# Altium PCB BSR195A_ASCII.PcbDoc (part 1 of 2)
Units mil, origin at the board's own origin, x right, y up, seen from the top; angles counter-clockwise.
Board outline 4000 x 3000 mil, 4 copper layers (Top Layer, Signal Layer 1, Signal Layer 2, Bottom Layer), stack 64.4 mil thick; 59 components, 14 nets, 91 pads, 35 vias.
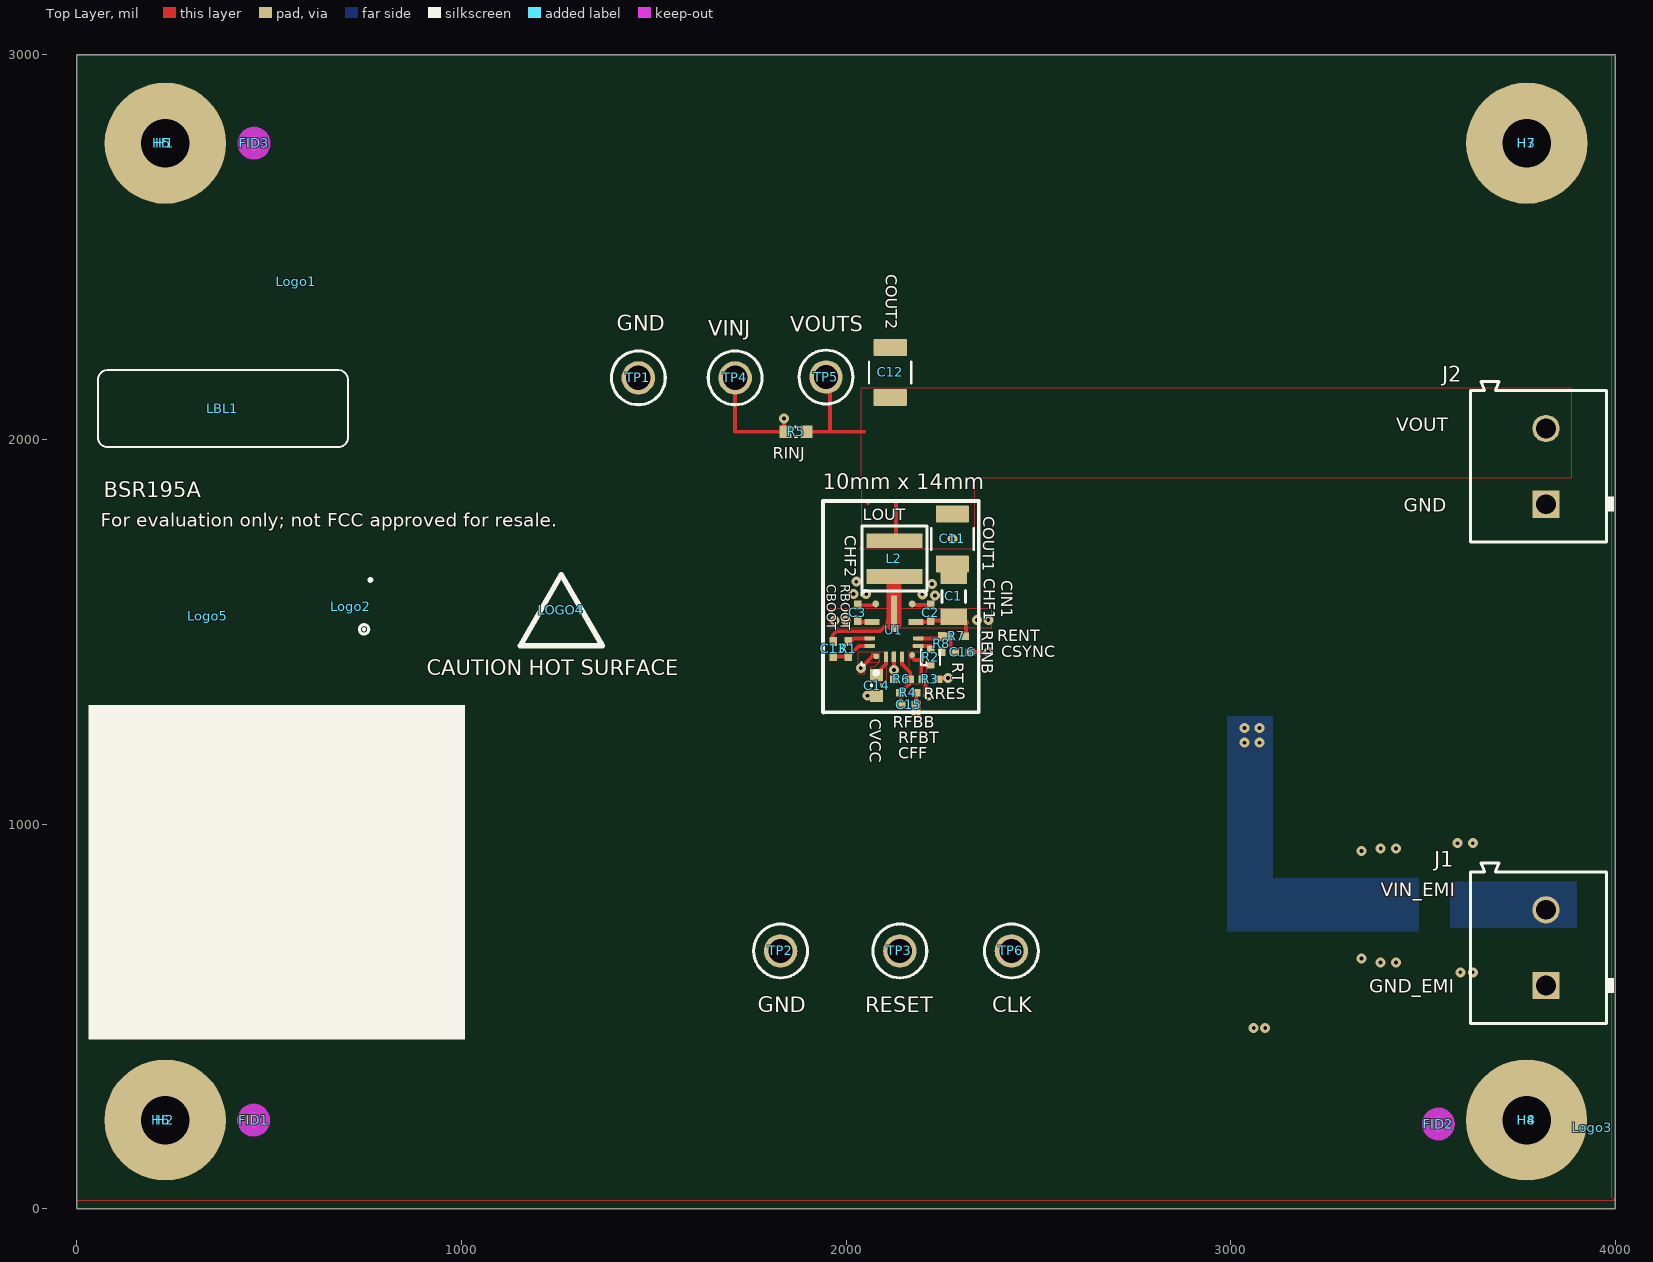
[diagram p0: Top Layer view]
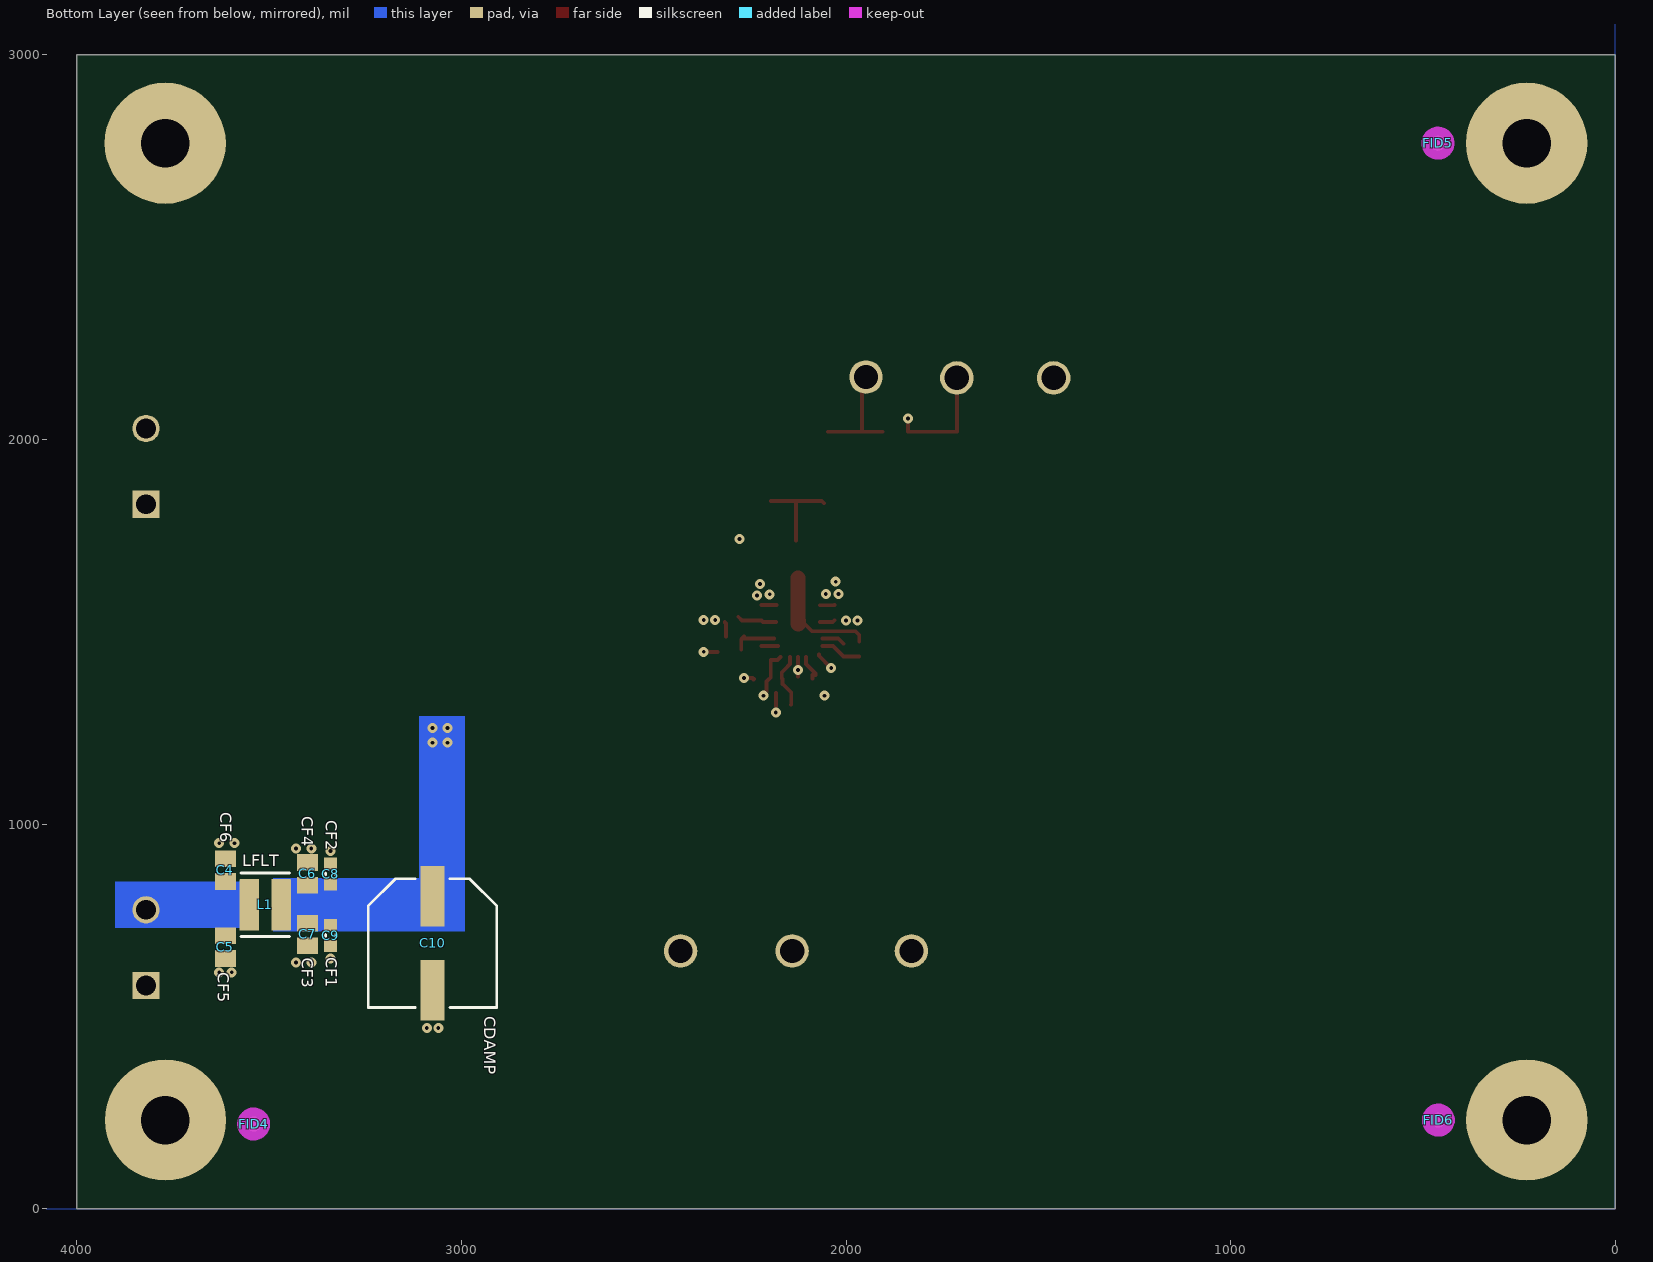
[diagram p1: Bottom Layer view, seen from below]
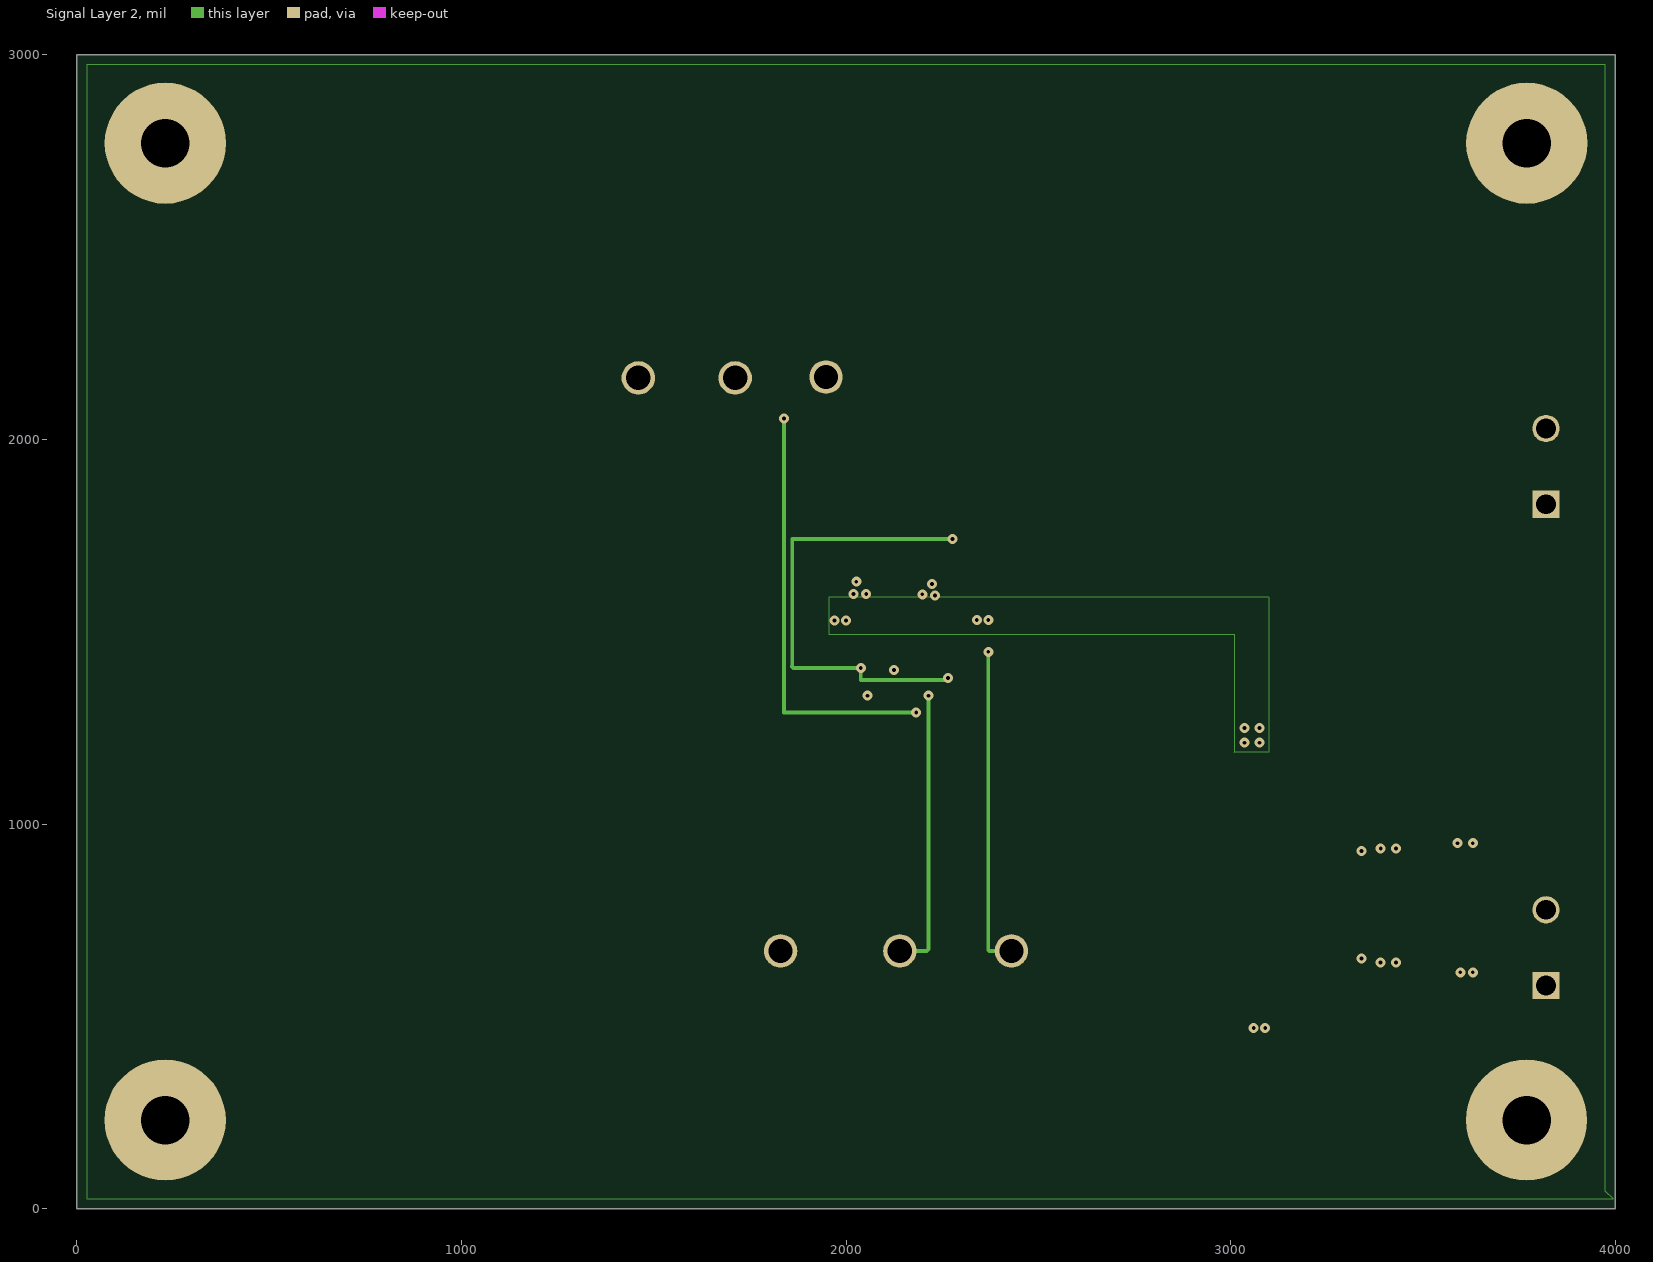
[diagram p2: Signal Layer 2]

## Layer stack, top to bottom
Top Solder: solder mask 0.4, Solder Resist, Dk 3.5
Top Layer: signal copper 2.8
Dielectric 1: prepreg 8, FR-4 High Tg, Dk 4.2
Signal Layer 1: signal copper 1.4
Dielectric 2: core 40, FR-4 High Tg, Dk 4.2
Signal Layer 2: signal copper 1.4
Dielectric 3: prepreg 8, FR-4 High Tg, Dk 4.2
Bottom Layer: signal copper 2.8
Bottom Solder: solder mask 0.4, Solder Resist, Dk 3.5

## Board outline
0,0 0,3000 4000,3000 4000,0

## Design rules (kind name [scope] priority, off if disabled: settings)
AcuteAngle [All] p0: scope1count=1 scope1_0_kind=Board scope1_0_value=Board scope2count=1 scope2_0_kind=Board scope2_0_value=Board commentlength=0 minimum=4.50000000000000E+0001
AcuteAngle [All] p1: minimum=4.50000000000000E+0001 checktracksonly=FALSE
AssemblyTestPointUsage [All] p0: scope1count=1 scope1_0_kind=Board scope1_0_value=Board scope2count=1 scope2_0_kind=Board scope2_0_value=Board commentlength=0
AssemblyTestPointUsage [All] p1: valid=2
AssemblyTestpoint [All] p0: scope1count=1 scope1_0_kind=Board scope1_0_value=Board scope2count=1 scope2_0_kind=Board scope2_0_value=Board commentlength=0
BoardOutlineClearance BoardOutlineClearance_MountingHoles [All] p0 off: scope1count=1 scope1_0_kind=Board scope1_0_value=Board scope2count=1 scope2_0_kind=Board scope2_0_value=Board commentlength=86 gap=40 // Protel DXP Scope 1 Expression Was: OnCopper and InComponentClass('Mounting Holes')
BoardOutlineClearance BoardOutlineClearance_Poly [All] p0 off: scope1count=1 scope1_0_kind=Board scope1_0_value=Board scope2count=1 scope2_0_kind=Board scope2_0_value=Board commentlength=58 gap=25 // Protel DXP Scope 1 Expression Was: OnCopper and IsPoly
BoardOutlineClearance [All] p0 off: scope1count=1 scope1_0_kind=Board scope1_0_value=Board scope2count=1 scope2_0_kind=Board scope2_0_value=Board commentlength=172 gap=65 // Protel DXP Scope 1 Expression Was: OnCopper and Not InComponentClass('Logo') and not InComponentClass('FiducialMark') and not InRegion(1000,500,4000,800) and not InPoly
BoardOutlineClearance BoardOutlineClearance_1 [All] p0: scope1count=1 scope1_0_kind=Footprint scope1_0_value=Edge_Connector_EDAC_12x2 scope2count=1 scope2_0_kind=Board scope2_0_value=Board commentlength=0 gap=0
BoardOutlineClearance BoardOutlineClearance_1 [HasFootprint('Edge_Connector_EDAC_12x2')] p1: gap=0 ignorepadtopadclearanceinfootprint=FALSE
BoardOutlineClearance BoardOutlineClearance_MountingHoles [OnCopper and InComponentClass('Mounting Holes')] p2: gap=40 ignorepadtopadclearanceinfootprint=FALSE
BoardOutlineClearance BoardOutlineClearance_Poly [OnCopper and IsPoly] p3: gap=25 ignorepadtopadclearanceinfootprint=FALSE
BoardOutlineClearance [OnCopper and Not InComponentClass('Logo') and not InComponentClass('FiducialMark') and not InRegion(1000,500,4000,800) and not InPoly] p4: gap=65 ignorepadtopadclearanceinfootprint=FALSE
Clearance "Stitching VIN_PIN" [All] p0 off: scope1count=1 scope1_0_kind=Board scope1_0_value=Board scope2count=1 scope2_0_kind=Board scope2_0_value=Board commentlength=80 gap=9 // Protel DXP Scope 2 Expression Was: (IsVia and (Not IsStitchingVia)) Or IsPad
Clearance Clearance_Keepouts [All] p0 off: scope1count=1 scope1_0_kind=Board scope1_0_value=Board scope2count=1 scope2_0_kind=Board scope2_0_value=Board commentlength=99 gap=0 // Protel DXP Scope 2 Expression Was: ((IsTrack Or IsArc) And Not InPoly) And IsFree and IsKeepOut
Clearance Clearance_Poly [All] p0 off: scope1count=1 scope1_0_kind=Board scope1_0_value=Board scope2count=1 scope2_0_kind=Board scope2_0_value=Board commentlength=48 gap=10 // Protel DXP Scope 1 Expression Was: InPolygon
Clearance Clearance_FiducialMark [All] p0 off: scope1count=1 scope1_0_kind=Board scope1_0_value=Board scope2count=1 scope2_0_kind=Board scope2_0_value=Board commentlength=81 gap=0 // Protel DXP Scope 2 Expression Was: IsPad and InComponentClass('FiducialMark')
Clearance [All] p0: scope1count=1 scope1_0_kind=Board scope1_0_value=Board scope2count=1 scope2_0_kind=Board scope2_0_value=Board commentlength=0 gap=7.87
Clearance "Stitching VIN_PIN" [IsStitchingVia and InNet('VIN_PIN') vs (IsVia and (Not IsStitchingVia)) Or IsPad] p1: gap=9 ignorepadtopadclearanceinfootprint=FALSE
Clearance Clearance_Keepouts [((IsTrack Or IsArc) And Not InPoly) And IsFree and IsKeepOut vs ((IsTrack Or IsArc) And Not InPoly) And IsFree and IsKeepOut] p2: gap=0 ignorepadtopadclearanceinfootprint=FALSE
Clearance Clearance_Poly [InPolygon] p3: gap=10 ignorepadtopadclearanceinfootprint=FALSE
Clearance Clearance_FiducialMark [IsKeepOut and InComponentClass('FiducialMark') vs IsPad and InComponentClass('FiducialMark')] p4: gap=0 ignorepadtopadclearanceinfootprint=FALSE
Clearance [All] p5: gap=7.87 ignorepadtopadclearanceinfootprint=FALSE except(0: Arc-Hole Track-Hole SMDPad-Hole THPad-Hole Via-Hole Fill-Hole Poly-Hole Region-Hole Text-Hole)
ComponentClearance ComponentClearance_Shunt [All] p0: scope1count=1 scope1_0_kind=ComponentClass scope1_0_value=Header scope2count=1 scope2_0_kind=ComponentClass scope2_0_value=Shunt commentlength=0 gap=0 collisioncheckmode=3
ComponentClearance ComponentClearance_Logo [All] p0: scope1count=1 scope1_0_kind=ComponentClass scope1_0_value=Logo scope2count=1 scope2_0_kind=Board scope2_0_value=Board commentlength=0 gap=50 collisioncheckmode=3
ComponentClearance ComponentClearance_ScrewToNut [All] p0 off: scope1count=1 scope1_0_kind=Board scope1_0_value=Board scope2count=1 scope2_0_kind=Board scope2_0_value=Board commentlength=71 gap=5 collisioncheckmode=3 // Protel DXP Scope 2 Expression Was: (HasFootprint('Keystone_1902C'))
ComponentClearance ComponentClearance_MountingHoles [All] p0: scope1count=1 scope1_0_kind=ComponentClass scope1_0_value="Mounting Holes" scope2count=1 scope2_0_kind=Board scope2_0_value=Board commentlength=0 gap=0 collisioncheckmode=3
ComponentClearance ComponentClearance_SmallPassives [All] p0 off: scope1count=1 scope1_0_kind=Board scope1_0_value=Board scope2count=1 scope2_0_kind=Board scope2_0_value=Board commentlength=508 gap=5 collisioncheckmode=3 // Protel DXP Scope 2 Expression Was: HasFootprint('0201*') or HasFootprint('0402*') or HasFootprint('0508') or HasFootprint('0603*') or HasFootprint('0612') or HasFootprint('0805*') or HasFootprint('0815*') or HasFootprint('0830*') or HasFootprint('1206*') or HasFootprint('1210*') or HasFootprint('1808*') or HasFootprint('1812*') or HasFootprint('1825*') or HasFootprint('2010*') or HasFootprint('2220*') or HasFootprint('2225*') or HasFootprint('2512*') or HasFootprint('2728*') or HasFootprint('3518*')
ComponentClearance ComponentClearance_THtoSMT [All] p0 off: scope1count=1 scope1_0_kind=Board scope1_0_value=Board scope2count=1 scope2_0_kind=Board scope2_0_value=Board commentlength=53 gap=40 collisioncheckmode=3 // Protel DXP Scope 2 Expression Was: IsSMTComponent
ComponentClearance ComponentClearance_THtoTH [All] p0 off: scope1count=1 scope1_0_kind=Board scope1_0_value=Board scope2count=1 scope2_0_kind=Board scope2_0_value=Board commentlength=54 gap=30 collisioncheckmode=3 // Protel DXP Scope 2 Expression Was: IsThruComponent
ComponentClearance [All] p0: scope1count=1 scope1_0_kind=Board scope1_0_value=Board scope2count=1 scope2_0_kind=Board scope2_0_value=Board commentlength=0 gap=5 collisioncheckmode=3
ComponentClearance ComponentClearance_1 [All] p0: scope1count=1 scope1_0_kind=Component scope1_0_value=SH-J1 scope2count=1 scope2_0_kind=Board scope2_0_value=Board commentlength=0 gap=0 collisioncheckmode=3
ComponentClearance ComponentClearance_1 [InComponent('SH-J1')] p1: gap=0 collisioncheckmode=3 verticalgap=0 showdistances=FALSE
ComponentClearance ComponentClearance_Shunt [InComponentClass('Header') vs InComponentClass('Shunt')] p2: gap=0 collisioncheckmode=3 verticalgap=0 showdistances=FALSE
ComponentClearance ComponentClearance_Logo [InComponentClass('Logo')] p3: gap=50 collisioncheckmode=3 verticalgap=10 showdistances=FALSE
ComponentClearance ComponentClearance_ScrewToNut [(HasFootprint('NY PMS 440 0025 PH')) vs (HasFootprint('Keystone_1902C'))] p4: gap=5 collisioncheckmode=3 verticalgap=10 showdistances=FALSE
ComponentClearance ComponentClearance_MountingHoles [InComponentClass('Mounting Holes')] p5: gap=0 collisioncheckmode=3 verticalgap=100000 showdistances=FALSE
ComponentClearance ComponentClearance_SmallPassives [HasFootprint('0201*') or HasFootprint('0402*') or HasFootprint('0508') or HasFootprint('0603*') or HasFootprint('0612') or HasFootprint('0805*') or HasFootprint('0815*') or HasFootprint('0830*') or HasFootprint('1206*') or HasFootprint('1210*') or HasFootprint('1808*') or HasFootprint('1812*') or HasFootprint('1825*') or HasFootprint('2010*') or HasFootprint('2220*') or HasFootprint('2225*') or HasFootprint('2512*') or HasFootprint('2728*') or HasFootprint('3518*') vs HasFootprint('0201*') or HasFootprint('0402*') or HasFootprint('0508') or HasFootprint('0603*') or HasFootprint('0612') or HasFootprint('0805*') or HasFootprint('0815*') or HasFootprint('0830*') or HasFootprint('1206*') or HasFootprint('1210*') or HasFootprint('1808*') or HasFootprint('1812*') or HasFootprint('1825*') or HasFootprint('2010*') or HasFootprint('2220*') or HasFootprint('2225*') or HasFootprint('2512*') or HasFootprint('2728*') or HasFootprint('3518*')] p6: gap=5 collisioncheckmode=3 verticalgap=10 showdistances=FALSE
ComponentClearance ComponentClearance_THtoSMT [IsThruComponent vs IsSMTComponent] p7: gap=40 collisioncheckmode=3 verticalgap=30 showdistances=FALSE
ComponentClearance ComponentClearance_THtoTH [IsThruComponent vs IsThruComponent] p8: gap=30 collisioncheckmode=3 verticalgap=30 showdistances=FALSE
ComponentClearance [All] p9: gap=5 collisioncheckmode=3 verticalgap=10 showdistances=FALSE
DiffPairsRouting [All] p0: scope1count=1 scope1_0_kind=Board scope1_0_value=Board scope2count=1 scope2_0_kind=Board scope2_0_value=Board commentlength=0
DiffPairsRouting [All] p1: maxlimit=100 minlimit=10 mostfreqgap=10 toplayer_minwidth=15 toplayer_maxwidth=15 toplayer_prefwidth=15 midlayer1_minwidth=15 midlayer1_maxwidth=15 midlayer1_prefwidth=15 midlayer2_minwidth=15 midlayer2_maxwidth=15 midlayer2_prefwidth=15 bottomlayer_minwidth=15 bottomlayer_maxwidth=15 bottomlayer_prefwidth=15 maxuncoupledlength=1000
FabricationTestPointUsage TestPointUsage [All] p0: scope1count=1 scope1_0_kind=Board scope1_0_value=Board scope2count=1 scope2_0_kind=Board scope2_0_value=Board commentlength=0 valid=2 allowmultiple=FALSE
FabricationTestPointUsage TestPointUsage [All] p1: valid=2 allowmultiple=FALSE
FabricationTestpoint Testpoint [All] p0: scope1count=1 scope1_0_kind=Board scope1_0_value=Board scope2count=1 scope2_0_kind=Board scope2_0_value=Board commentlength=0 side=3 testpointundercomponent=TRUE minsize=40 maxsize=100 preferedsize=60 minholesize=0 maxholesize=40 preferedholesize=32 testpointgrid=1
FabricationTestpoint Testpoint [All] p1: side=3 testpointundercomponent=TRUE minsize=40 maxsize=100 preferedsize=60 minholesize=0 maxholesize=40 preferedholesize=32 testpointgrid=1 allowsidetop=TRUE allowsidebottom=TRUE usegrid=TRUE gridtolerance=0.01
FanoutControl Fanout_LCC [All] p0 off: scope1count=1 scope1_0_kind=Board scope1_0_value=Board scope2count=1 scope2_0_kind=Board scope2_0_value=Board commentlength=69 // Protel DXP Scope 1 Expression Was: IsLCC   Fanout_LCC (Default Rule)
FanoutControl Fanout_BGA [All] p0 off: scope1count=1 scope1_0_kind=Board scope1_0_value=Board scope2count=1 scope2_0_kind=Board scope2_0_value=Board commentlength=69 // Protel DXP Scope 1 Expression Was: IsBGA   Fanout_BGA (Default Rule)
FanoutControl Fanout_SOIC [All] p0 off: scope1count=1 scope1_0_kind=Board scope1_0_value=Board scope2count=1 scope2_0_kind=Board scope2_0_value=Board commentlength=71 // Protel DXP Scope 1 Expression Was: IsSOIC   Fanout_SOIC (Default Rule)
FanoutControl Fanout_Default [All] p0: scope1count=1 scope1_0_kind=Board scope1_0_value=Board scope2count=1 scope2_0_kind=Board scope2_0_value=Board commentlength=30 // Fanout_Default (Default Rule)
FanoutControl Fanout_Small [All] p0 off: scope1count=1 scope1_0_kind=Board scope1_0_value=Board scope2count=1 scope2_0_kind=Board scope2_0_value=Board commentlength=84 // Protel DXP Scope 1 Expression Was: (CompPinCount < 5)   Fanout_Small (Default Rule)
FanoutControl Fanout_LCC [IsLCC] p1: bgadir=Out bgaviamode=Centered fanoutstyle=Auto fanoutdirection=Alternating viagrid=1 // Fanout_LCC (Default Rule)
FanoutControl Fanout_BGA [IsBGA] p2: bgadir=Out bgaviamode=Centered fanoutstyle=Auto fanoutdirection=Alternating viagrid=1 // Fanout_BGA (Default Rule)
FanoutControl Fanout_Default [All] p4: bgadir=Out bgaviamode=Centered fanoutstyle=Auto fanoutdirection=Alternating viagrid=1 // Fanout_Default (Default Rule)
FanoutControl Fanout_Small [(CompPinCount < 5)] p5: bgadir=Out bgaviamode=Centered fanoutstyle=Auto fanoutdirection=OutThenIn viagrid=1 // Fanout_Small (Default Rule)
Height [All] p0: scope1count=1 scope1_0_kind=Board scope1_0_value=Board scope2count=1 scope2_0_kind=Board scope2_0_value=Board commentlength=0
HoleSize [All] p0: scope1count=1 scope1_0_kind=Board scope1_0_value=Board scope2count=1 scope2_0_kind=Board scope2_0_value=Board commentlength=0 absolutevalues=TRUE maxlimit=251 minlimit=7.87 maxpercent=80.000 minpercent=20.000
HoleSize [All] p1: absolutevalues=TRUE maxlimit=251 minlimit=7.87 maxpercent=80.000 minpercent=20.000
HoleToHoleClearance [All] p0: scope1count=1 scope1_0_kind=Board scope1_0_value=Board scope2count=1 scope2_0_kind=Board scope2_0_value=Board commentlength=0
LayerPairs [All] p0: scope1count=1 scope1_0_kind=Board scope1_0_value=Board scope2count=1 scope2_0_kind=Board scope2_0_value=Board commentlength=0 enforce=TRUE
MinimumAnnularRing MinimumAnnularRing_ThermalPadVias [All] p0 off: scope1count=1 scope1_0_kind=Board scope1_0_value=Board scope2count=1 scope2_0_kind=Board scope2_0_value=Board commentlength=63 minimumring=5.91 // Protel DXP Scope 1 Expression Was: IsVia and InAnyComponent
MinimumAnnularRing [All] p0: scope1count=1 scope1_0_kind=Board scope1_0_value=Board scope2count=1 scope2_0_kind=Board scope2_0_value=Board commentlength=0 minimumring=8
MinimumAnnularRing MinimumAnnularRing_ThermalPadVias [IsVia and InAnyComponent] p1: minimumring=5.91
MinimumAnnularRing [All] p2: minimumring=8
MinimumSolderMaskSliver MinimumSolderMaskSliver_Logo [All] p0: scope1count=1 scope1_0_kind=ComponentClass scope1_0_value=Logo scope2count=1 scope2_0_kind=ComponentClass scope2_0_value=Logo commentlength=0
MinimumSolderMaskSliver [All] p0: scope1count=1 scope1_0_kind=Board scope1_0_value=Board scope2count=1 scope2_0_kind=Board scope2_0_value=Board commentlength=0
MinimumSolderMaskSliver MinimumSolderMaskSliver_Logo [InComponentClass('Logo') vs InComponentClass('Logo')] p1: minsoldermaskwidth=0.7
MinimumSolderMaskSliver [All] p2: minsoldermaskwidth=3.94
NetAntennae [All] p0: scope1count=1 scope1_0_kind=Board scope1_0_value=Board scope2count=1 scope2_0_kind=Board scope2_0_value=Board commentlength=0
PasteMaskExpansion [All] p0: scope1count=1 scope1_0_kind=Board scope1_0_value=Board scope2count=1 scope2_0_kind=Board scope2_0_value=Board commentlength=0 expansion=0
PlaneClearance [All] p0: scope1count=1 scope1_0_kind=Board scope1_0_value=Board scope2count=1 scope2_0_kind=Board scope2_0_value=Board commentlength=0 clearance=20
PlaneConnect [All] p0: scope1count=1 scope1_0_kind=Board scope1_0_value=Board scope2count=1 scope2_0_kind=Board scope2_0_value=Board commentlength=0 planeconnectstyle=Direct reliefexpansion=10 reliefentries=4 reliefconductorwidth=10 reliefairgap=10
PlaneConnect [All] p1: planeconnectstyle=Direct reliefexpansion=10 reliefentries=4 reliefconductorwidth=10 reliefairgap=10
PolygonConnect [All] p0: scope1count=1 scope1_0_kind=Board scope1_0_value=Board scope2count=1 scope2_0_kind=Board scope2_0_value=Board commentlength=0 connectstyle=Direct reliefconductorwidth=10 reliefentries=4 polygonreliefangle="90 Angle"
PolygonConnect [All] p1: connectstyle=Direct reliefconductorwidth=10 reliefentries=4 polygonreliefangle="90 Angle" airgapwidth=10
RoutingCorners [All] p0: scope1count=1 scope1_0_kind=Board scope1_0_value=Board scope2count=1 scope2_0_kind=Board scope2_0_value=Board commentlength=0 cornerstyle=45-Degree minsetback=100 maxsetback=100
RoutingLayers [All] p0: scope1count=1 scope1_0_kind=Board scope1_0_value=Board scope2count=1 scope2_0_kind=Board scope2_0_value=Board commentlength=0 top layer=Automatic mid layer 1=Automatic mid layer 2=Automatic bottom layer=Automatic
RoutingPriority [All] p0: scope1count=1 scope1_0_kind=Board scope1_0_value=Board scope2count=1 scope2_0_kind=Board scope2_0_value=Board commentlength=0
RoutingTopology [All] p0: scope1count=1 scope1_0_kind=Board scope1_0_value=Board scope2count=1 scope2_0_kind=Board scope2_0_value=Board commentlength=0 topology=Shortest
RoutingVias ThermalPadVias [All] p0 off: scope1count=1 scope1_0_kind=Board scope1_0_value=Board scope2count=1 scope2_0_kind=Board scope2_0_value=Board commentlength=63 holewidth=7.87 width=19.68 viastyle="Through Hole" minholewidth=7.87 minwidth=19.68 maxholewidth=12.99 maxwidth=23.62 // Protel DXP Scope 1 Expression Was: IsVia and InAnyComponent
RoutingVias [All] p0: scope1count=1 scope1_0_kind=Board scope1_0_value=Board scope2count=1 scope2_0_kind=Board scope2_0_value=Board commentlength=0 holewidth=16 width=34 viastyle="Through Hole" minholewidth=7.87 minwidth=26 maxholewidth=40 maxwidth=65
RoutingVias ThermalPadVias [IsVia and InAnyComponent] p1: holewidth=7.87 width=19.68 viastyle="Through Hole" minholewidth=7.87 minwidth=19.68 maxholewidth=12.99 maxwidth=23.62
RoutingVias [All] p2: holewidth=16 width=34 viastyle="Through Hole" minholewidth=7.87 minwidth=26 maxholewidth=40 maxwidth=65
ShortCircuit [All] p0: scope1count=1 scope1_0_kind=Board scope1_0_value=Board scope2count=1 scope2_0_kind=Board scope2_0_value=Board commentlength=0 allowed=FALSE
SilkToBoardRegionClearance [All] p0 off: scope1count=1 scope1_0_kind=Board scope1_0_value=Board scope2count=1 scope2_0_kind=Board scope2_0_value=Board commentlength=130 // Protel DXP Scope 1 Expression Was: Not ((IsComment or IsDesignator) And (Hide <> 'False')) and not InRegion(1000,500,4000,800)
SilkToBoardRegionClearance [Not ((IsComment or IsDesignator) And (Hide <> 'False')) and not InRegion(1000,500,4000,800)] p1:
SilkToSilkClearance SilkToSilkClearance_Pb-FreeLogo [All] p0 off: scope1count=1 scope1_0_kind=Board scope1_0_value=Board scope2count=1 scope2_0_kind=Board scope2_0_value=Board commentlength=120 // Protel DXP Scope 2 Expression Was: (HasFootprint('Pb-Free_Overlay_Medium') OR HasFootprint('Pb-Free_Overlay_Small'))
SilkToSilkClearance [All] p0: scope1count=1 scope1_0_kind=Board scope1_0_value=Board scope2count=1 scope2_0_kind=Board scope2_0_value=Board commentlength=0
SilkToSilkClearance SilkToSilkClearance_Pb-FreeLogo [(HasFootprint('Pb-Free_Overlay_Medium') OR HasFootprint('Pb-Free_Overlay_Small')) vs (HasFootprint('Pb-Free_Overlay_Medium') OR HasFootprint('Pb-Free_Overlay_Small'))] p1: silktosilkclearance=0
SilkToSilkClearance [All] p2: silktosilkclearance=4
SilkToSolderMaskClearance SilkToComponentPadClearance [All] p0 off: scope1count=1 scope1_0_kind=Board scope1_0_value=Board scope2count=1 scope2_0_kind=Board scope2_0_value=Board commentlength=87 // Protel DXP Scope 1 Expression Was: (IsPad or IsFill or IsRegion) and InAnycomponent
SilkToSolderMaskClearance "Silk to Solder Mask Opening" [All] p0: scope1count=1 scope1_0_kind=Board scope1_0_value=Board scope2count=1 scope2_0_kind=Board scope2_0_value=Board commentlength=0
SilkToSolderMaskClearance SilkToComponentPadClearance [(IsPad or IsFill or IsRegion) and InAnycomponent] p1: minsilkscreentomaskgap=5 clearancetoexposedcopper=TRUE
SilkToSolderMaskClearance "Silk to Solder Mask Opening" [All] p2: minsilkscreentomaskgap=4 clearancetoexposedcopper=FALSE
SolderMaskExpansion [All] p0: scope1count=1 scope1_0_kind=Board scope1_0_value=Board scope2count=1 scope2_0_kind=Board scope2_0_value=Board commentlength=0 expansion=1.97
SolderMaskExpansion [All] p1: expansion=1.97
UnRoutedNet [All] p0: scope1count=1 scope1_0_kind=Board scope1_0_value=Board scope2count=1 scope2_0_kind=Board scope2_0_value=Board commentlength=0
UnpouredPolygon [All] p0: scope1count=1 scope1_0_kind=Board scope1_0_value=Board scope2count=1 scope2_0_kind=Board scope2_0_value=Board commentlength=0
Width [All] p0: scope1count=1 scope1_0_kind=Board scope1_0_value=Board scope2count=1 scope2_0_kind=Board scope2_0_value=Board commentlength=0 maxlimit=200 minlimit=6 preferedwidth=10
Width [All] p1: maxlimit=200 minlimit=6 preferedwidth=10 checkconnectedcopper=TRUE
15 further rules are at their usual default settings.

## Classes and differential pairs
component class Label: LBL1
component class BSR195A: C1 C2 C3 C4 C5 C6 C7 C8 C9 C10 C11 C12 C13 C14 C15 C16 C17 C18 C19 D1 J1 J2 J7 L1 L2 L-FLT L? PL1 R1 R2 R3 R4 R5 R6 R7 R8 R10 R13 R14 R15 R? TP1 TP2 TP3 TP4 TP5 TP6 TP11 TP13 TP17 TP? U1
component class Logo: Logo1
component class AssemblyNote: ZZ1 ZZ2 ZZ3 ZZ4
component class BSR195A_Hardware: !PCB FID1 FID2 FID3 FID4 FID5 FID6 H1 H2 H3 H4 H5 H6 H7 H8 LBL1 Logo1 Logo2 Logo3 LOGO4 Logo4 Logo5 Logo10 ZZ1 ZZ2 ZZ3 ZZ4
component class FiducialMark: FID1 FID2 FID3 FID4 FID5 FID6
component class "Mounting Holes": H1 H2 H3 H4

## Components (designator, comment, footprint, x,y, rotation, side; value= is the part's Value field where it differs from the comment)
C1 "CIN1" 1206_180L 2280,1591.89 r90 top
C2 "CHF1" 0402L 2220,1549 r90 top
C3 "CHF2" 0402L 2030,1549.5 r90 top
C4 "CF6" 0805L 3613.51,880 r90 bottom
C5 "CF5" 0805L 3613.51,680 r270 bottom
C6 "CF4" 0805L 3400,870.2 r90 bottom
C7 "CF3" 0805L 3400,712.79 r270 bottom
C8 "CF2" 0603L 3340,870 r90 bottom
C9 "CF1" 0603L 3340,710 r270 bottom
C10 "CDAMP" SM_RADIAL_E 3075.02,690.32 r270 bottom
C11 "COUT1" FP-CGA6P1X7S1A476M250AC_1210-MFG 2276.75,1741.11 r270 top
C12 "COUT2" FP-CGA6P1X7S1A476M250AC_1210-MFG 2114.77,2173.97 r90 top
C13 "CBOOT" 0402L 1966.55,1455.1 r90 top
C14 "CVCC" 0603L 2079.35,1360 r270 top
C15 "CFF" 0402L 2162.81,1310 r180 top
C16 "CSYNC" 0402L 2302.32,1446.97 r0 top
FID1 "Fiducial" Fiducial10-20 460,230 r0 top
FID2 "Fiducial" Fiducial10-20 3540,220 r90 top
FID3 "Fiducial" Fiducial10-20 460.95,2770 r90 top
FID4 "Fiducial" Fiducial10-20 3540,220 r180 bottom
FID5 "Fiducial" Fiducial10-20 460.95,2770 r180 bottom
FID6 "Fiducial" Fiducial10-20 460,230 r180 bottom
H1 "NY PMS 440 0025 PH" "NY PMS 440 0025 PH" 230.13,2770 r90 top
H2 "NY PMS 440 0025 PH" "NY PMS 440 0025 PH" 230,230 r90 top
H3 "NY PMS 440 0025 PH" "NY PMS 440 0025 PH" 3770,2770 r90 top
H4 "NY PMS 440 0025 PH" "NY PMS 440 0025 PH" 3769.5,230 r90 top
H5 "1902C" Keystone_1902C 222.49,2770 r90 top
H6 "1902C" Keystone_1902C 219.09,230 r90 top
H7 "1902C" Keystone_1902C 3770,2770 r90 top
H8 "1902C" Keystone_1902C 3769.49,229.77 r90 top
J1 "691 101 710 002" Wurth_691101710002 3820,678.43 r90 top
J2 "691 101 710 002" Wurth_691101710002 3820,1930 r90 top
L1 "LFLT" FP-74438336010_SMD2-MFG 3510,790 r180 bottom
L2 "LOUT" WE-MAPI_4020 2126.03,1690 r90 top
LBL1 "THT-14-423-10" Label_650x200 380,2080 r180 top
Logo1 "Texas Instruments" TI_Stacked_Overlay_Small 570,2410 r0 top
Logo2 "WEEE logo" WEEE_Minimum 712.86,1564.5 r0 top
Logo3 "FCC disclaimer" FCC_disclaimer 3940,210 r90 top
LOGO4 "CAUTION HOT SURFACE" IEC_HotSurface_Small 1260,1556.37 r0 top
Logo5 "CAUTION HOT SURFACE" CE_Mark_5mm 340,1540 r0 top
R1 "RBOOT" 0402L 2006.12,1455.1 r90 top
R2 "RT" FP-ERJ-2RKF5901X_0402-MFG 2220,1433.97 r90 top
R3 "RRES" 0402L 2219.43,1376.7 r180 top
R4 "RFBT" 0402L 2162.03,1341.3 r0 top
R5 "RINJ" 0603L 1870,2020 r180 top
R6 "RFBB" 0402L 2145.29,1376.7 r180 top
R7 "RENT" 0402L 2288.54,1487.69 r0 top
R8 "RENB" 0402L 2249.49,1468 r90 top
TP1 "GND" Keystone5011 1460,2160 r90 top
TP2 "GND" Keystone5011 1830,670 r90 top
TP3 "RESET" Keystone5012 2140,670 r0 top
TP4 "VINJ" Keystone5013 1711.84,2160 r90 top
TP5 "VOUTS" Keystone5010 1948.02,2162.02 r90 top
TP6 "CLK" Keystone5013 2430,670 r90 top
U1 "LM61430AASQRJRRQ1" RJR0014A-MFG 2124.62,1507.24 r90 top
ZZ1 "These assemblies are ESD sensitive, ESD precautions shall be observed." AssemblyNote 280,3720 r0 top
ZZ2 "These assemblies must be clean and free from flux and all contaminants. Use of no clean flux is not acceptable." AssemblyNote 280,3600 r0 top
ZZ3 "These assemblies must comply with workmanship standards IPC-A-610 Class 2, unless otherwise specified." AssemblyNote 280,3480 r0 top
ZZ4 "Inductor L2 should be populated with dot of componet facing IC." AssemblyNote 280,3230 r90 top

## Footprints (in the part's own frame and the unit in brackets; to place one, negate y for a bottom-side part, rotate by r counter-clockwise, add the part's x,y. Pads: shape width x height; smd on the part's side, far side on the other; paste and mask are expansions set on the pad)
0402L [mm] "0402 from SM-752 data"
  rect 0.6x0.5 smd: 1(-0.5,0) 2(0.5,0)
0603L [mm] "0603 from SM-752 data"
  rect 0.8x0.85 smd: 1(-0.7,0) 2(0.7,0)
  silkscreen extent -0.07,-0.33 0.07,0.33
0805L [mm] "0805 from SM-752 data"
  rect 1.1x1.4 smd: 1(-0.75,0) 2(0.75,0)
1206_180L [mm] "1206_180"
  rect 1.1x1.75 smd: 1(-1.35,0) 2(1.35,0)
  silkscreen extent -0.4,-0.77 0.4,0.77
AssemblyNote [mil] "Assembly Note"
CE_Mark_5mm [mil] "Minimum text height for CE Mark"
FCC_disclaimer [mil]
Fiducial10-20 [mm]
  round 1 smd mask+0: 1(0,0)
  Top Layer keep-out circle w1.178: c0,0 r0.5
FP-74438336010_SMD2-MFG [mm]
  rrect8% 1.3x3.4 smd paste+0 mask+0: 1(-1.05,0) 2(1.05,0)
  silkscreen extent -1.6,-2.1 1.6,2.1
FP-CGA6P1X7S1A476M250AC_1210-MFG [mm]
  rrect9% 1.1x2.2 smd paste+0 mask+0: 1(-1.65,0) 2(1.65,0)
  silkscreen extent -0.72,-1.4 0.72,1.4
FP-ERJ-2RKF5901X_0402-MFG [mm]
  rrect21% 0.475x0.5 smd paste+0 mask+0: 1(-0.513,0) 2(0.513,0)
  silkscreen extent -0.53,-0.63 0.53,0.63
IEC_HotSurface_Small [mil]
  silkscreen extent -107,-93 107,92
Keystone5010 [mil] "Keystone Multipurpose loops"
  round 87 hole 63: 1(0,0)
  silkscreen extent -70,-70 70,70
Keystone5011 [mil] "Keystone Multipurpose loops"
  round 87 hole 63: 1(0,0)
  silkscreen extent -70,-70 70,70
Keystone5012 [mil] "Keystone Multipurpose loops"
  round 87 hole 63: 1(0,0)
  silkscreen extent -70,-70 70,70
Keystone5013 [mil] "Keystone Multipurpose loops"
  round 87 hole 63: 1(0,0)
  silkscreen extent -70,-70 70,70
Keystone_1902C [mil] "Hex Standoff, 4-40 threaded, nylon"
  round 1 on Mech3: 0(0,0)
Label_650x200 [mil] "Thermal Transfer Label"
  round 1 on Mech13: 0(0,0)
  silkscreen extent -325,-100 325,100
"NY PMS 440 0025 PH" [mm] "4-40 nylon screw and mounting hole"
  round 8 hole 3.2: 1(0,0)
RJR0014A-MFG [mm]
  round 0.394 smd paste-1000 mask+0: 1(-1.806,1.169) 5(-1.719,-1.206)
  rrect40% 0.7x0.25 smd paste+0 mask+0: 2(-1.85,0.525) 4(-1.85,-0.525)
  rrect33% 0.7x0.3 smd paste+0 mask+0: 3(-1.85,0)
  rrect40% 0.25x0.7 smd paste+0 mask+0: 6(-1.125,-1.6) 7(-0.625,-1.6) 13(-0.625,1.6) 14(-1.125,1.6)
  rrect25% 0.4x1 smd paste+0 mask+0: 8(0.45,-1.45) 12(0.45,1.45)
  round 0.45 smd paste-1000 mask+0: 9(1.65,-1.2) 11(1.65,1.2)
  rrect25% 2.4x0.4 smd paste-1000 mask+0: 10(1,0)
  silkscreen extent -3.02,-2.15 2.4,2.15
SM_RADIAL_E [mm] "8 x 6.2mm:  Panasonic E"
  rect 4x1.6 smd: 1(-3.1,0) 2(3.1,0)
  silkscreen extent -4.25,-4.25 4.25,4.25
TI_Stacked_Overlay_Small [mil]
WE-MAPI_4020 [mm] "SMD, 2-Leads, Body 4.1x4.1mm"
  rect 0.98x3.7 smd: 1(-1.185,0) 2(1.185,0)
  silkscreen extent -2.15,-2.15 2.15,2.15
WEEE_Minimum [mil] "WEEElie bin"
  silkscreen extent 22,-71 54,74
Wurth_691101710002 [mm] "Terminal Block, 5 mm, 2x1, TH"
  rect 1.8x1.8 hole 1.3: 1(-2.5,0)
  round 1.8 hole 1.3: 2(2.5,0)
  silkscreen extent -5,-4.5 5.6,5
